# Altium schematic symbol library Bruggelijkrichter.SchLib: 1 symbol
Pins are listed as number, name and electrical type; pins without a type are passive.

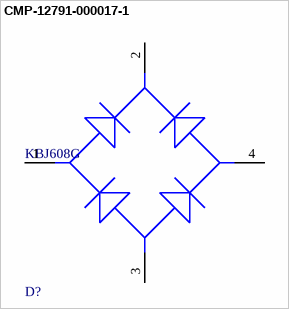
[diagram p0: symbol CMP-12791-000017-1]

## CMP-12791-000017-1
designator D?, comment KBJ608G
BRIDGE RECT 1PHASE 800V 6A KBJ; Manufacturer: Diodes; Max Junction Temp: +150°C; Max Surge Forward Current: 170A; Peak Reverse Current: 5uA; Standoff Height: 3.3mm; Value: 80pF; Forward Current: 3A
footprint FP-KBJ-MFG
pins: 1 +, 2 1 ~, 3 2 ~, 4 -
